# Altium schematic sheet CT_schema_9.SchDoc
size 382 x 278 mm
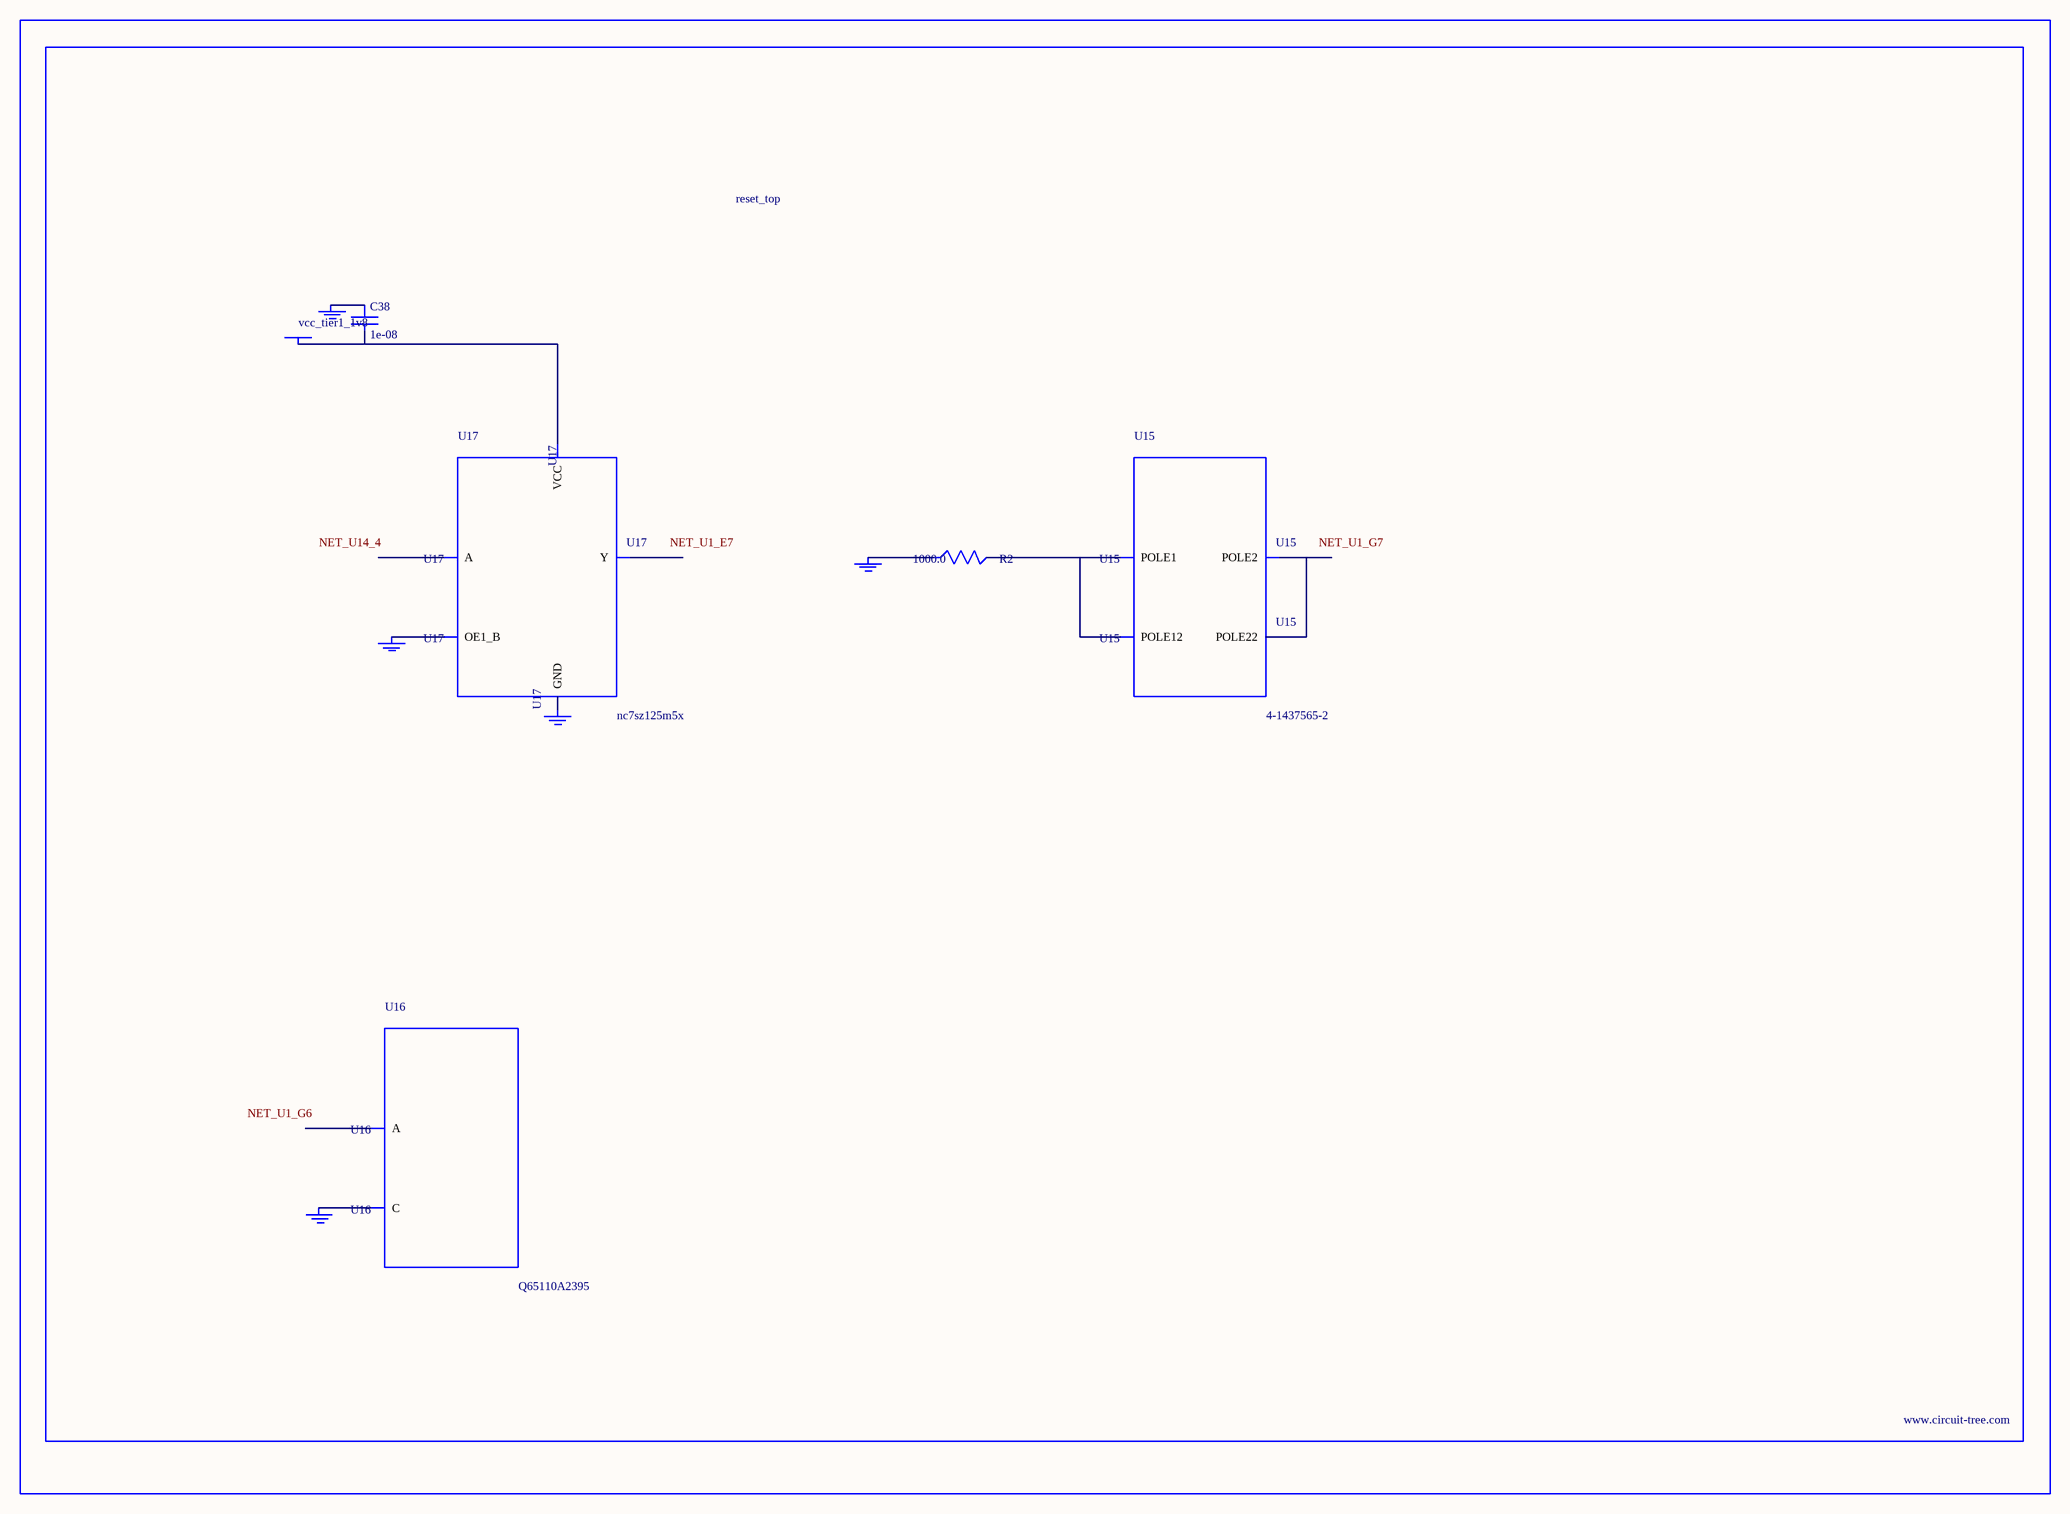
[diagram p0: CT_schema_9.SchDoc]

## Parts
BORDER8  (no value)
C38  1e-08  [C0402]
GND_INSTANCE_8_0  (no value)
GND_INSTANCE_8_1  (no value)
GND_INSTANCE_8_2  (no value)
GND_INSTANCE_8_3  (no value)
GND_INSTANCE_8_4  (no value)
POWER_INSTANCE_8_0  vcc_tier1_1v8
R2  1000.0  [R0603]
U15  4-1437565-2  [SW_4-1437565-2]
U16  Q65110A2395  [LGM67K-G1J2-24-Z]
U17  nc7sz125m5x  [NC7SZ125M5X]

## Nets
NetC38_1: C38.1 GND_INSTANCE_8_2.0(GND)
NetC38_2: C38.2 POWER_INSTANCE_8_0.0(PWR) U17.5(VCC)
NetGND_INSTANCE_8_0_0: GND_INSTANCE_8_0.0(GND) R2.1
NetGND_INSTANCE_8_1_0: GND_INSTANCE_8_1.0(GND) U16.C
NetGND_INSTANCE_8_3_0: GND_INSTANCE_8_3.0(GND) U17.1(OE1_B)
NetGND_INSTANCE_8_4_0: GND_INSTANCE_8_4.0(GND) U17.3(GND)
NetR2_2: R2.2 U15.1(POLE1) U15.2(POLE12)
NetU15_3: U15.3(POLE2) U15.4(POLE22)

Not connected (* = marked no-connect by the designer): U16 A; U17 2(A) 4(Y)

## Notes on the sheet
- Labels drawn without touching a wire or pin: NET_U1_E7, NET_U1_G6, NET_U1_G7, NET_U14_4

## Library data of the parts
BORDER8 = BORDER_PAGE8
C38 = C0402C103K3RAC
GND_INSTANCE_8_0-GND_INSTANCE_8_4 = GND
POWER_INSTANCE_8_0 = PWR
R2 = RC0603JR-071KL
